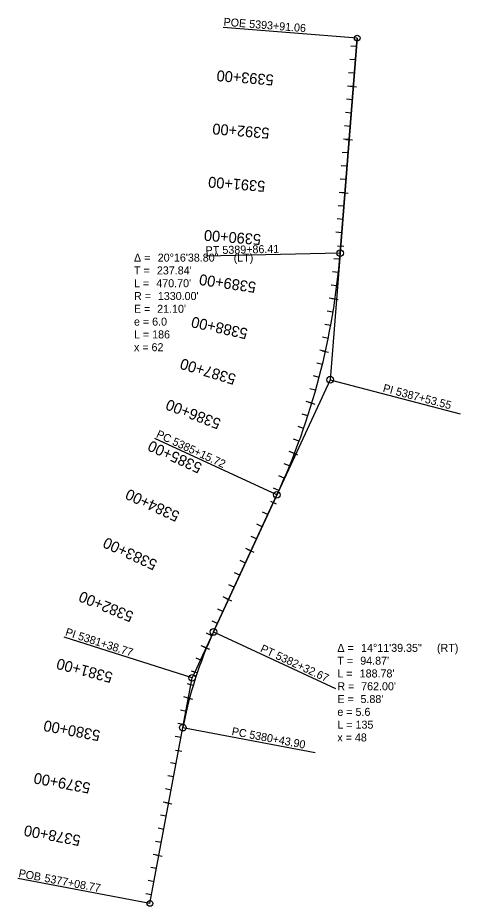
# Model space of a CAD drawing. Extents: x 20505953 to 20506782, y 7970566 to 7972232.
import ezdxf

# ---------------------------------------------------------------- set-up
doc = ezdxf.new("R2010")
doc.units = 0
for name, color, linetype in [('Alignment', 7, 'Continuous'), ('TextAlignment', 7, 'Continuous'), ('TextAlignmentLrg', 7, 'Continuous'), ('TextAlignmentSml', 7, 'Continuous')]:
    doc.layers.add(name, color=color, linetype=linetype)

msp = doc.modelspace()

# ---------------------------------------------------------------- linework, layer by layer
at = {"layer": 'Alignment'}
for p, q in [((20506589.2, 7972193.7), (20506538.4, 7971553.3)), ((20506589.2, 7972193.7), (20506557.2, 7971790.4)), ((20506557.2, 7971790.4), (20506589.2, 7972193.7)), ((20506538.4, 7971553.3), (20506280, 7970994.4)), ((20506319.9, 7971080.5), (20506438.6, 7971337.4)), ((20506200.8, 7970571.7), (20506280, 7970994.4)), ((20506200.8, 7970571.7), (20506262.6, 7970901.1)), ((20506200.8, 7970571.7), (20506262.6, 7970901.1))]:
    msp.add_line(p, q, dxfattribs=at)
for centre, radius, start, end in [((20505231.4, 7971895.5), 1330, 335.1875, 355.465), ((20505231.4, 7971895.5), 1330, 335.1875, 355.465), ((20507011.5, 7970760.7), 762, 155.1875, 169.3818), ((20507011.5, 7970760.7), 762, 155.1875, 169.3818)]:
    msp.add_arc(centre, radius, start, end, dxfattribs=at)
at = {"layer": 'TextAlignment'}
for p, q in [((20506589.2, 7972193.7), (20506338, 7972213.7)), ((20506338, 7972213.7), (20506338, 7972213.7)), ((20506306, 7971810.3), (20506306, 7971810.3)), ((20506557.2, 7971790.4), (20506305.3, 7971785)), ((20506538.4, 7971553.3), (20506782.2, 7971489.4)), ((20506782.2, 7971489.4), (20506782.2, 7971489.4)), ((20506438.6, 7971337.4), (20506209.9, 7971443.1)), ((20506209.9, 7971443.1), (20506209.9, 7971443.1)), ((20506280, 7970994.4), (20506040, 7971071)), ((20506040, 7971071), (20506040, 7971071)), ((20506319.9, 7971080.5), (20506548.6, 7970974.7)), ((20506548.6, 7970974.7), (20506548.6, 7970974.7)), ((20506262.6, 7970901.1), (20506510.2, 7970854.7)), ((20506510.2, 7970854.7), (20506510.2, 7970854.7)), ((20506200.8, 7970571.7), (20505953.1, 7970618.2)), ((20505953.1, 7970618.2), (20505953.1, 7970618.2))]:
    msp.add_line(p, q, dxfattribs=at)
for centre, radius in [((20506589.2, 7972193.7), 5.34), ((20506557.2, 7971790.4), 6.24), ((20506538.4, 7971553.3), 6.24), ((20506438.6, 7971337.4), 6.24), ((20506319.9, 7971080.5), 6.24), ((20506280, 7970994.4), 6.24), ((20506262.6, 7970901.1), 6.24), ((20506200.8, 7970571.7), 5.34)]:
    msp.add_circle(centre, radius, dxfattribs=at)
at = {"layer": 'TextAlignmentLrg'}
for p, q in [((20506582, 7972103), (20506571.2, 7972103.8)), ((20506574.1, 7972003.3), (20506563.2, 7972004.1)), ((20506566.2, 7971903.6), (20506555.3, 7971904.4)), ((20506552.2, 7971804.4), (20506564.4, 7971803.4)), ((20506547.6, 7971704.5), (20506536.8, 7971706.1)), ((20506529.6, 7971606.2), (20506518.9, 7971608.5)), ((20506504.1, 7971509.5), (20506493.7, 7971512.6)), ((20506471.6, 7971415), (20506461.4, 7971418.9)), ((20506426.5, 7971325.7), (20506437.6, 7971320.5)), ((20506390.1, 7971232.3), (20506380.2, 7971236.9)), ((20506348.1, 7971141.6), (20506338.2, 7971146.2)), ((20506306.8, 7971050.5), (20506296.7, 7971054.7)), ((20506274.9, 7970955.8), (20506264.4, 7970958.6)), ((20506248.5, 7970859.1), (20506260.5, 7970856.8)), ((20506236, 7970759.7), (20506225.3, 7970761.7)), ((20506217.6, 7970661.4), (20506206.9, 7970663.4))]:
    msp.add_line(p, q, dxfattribs=at)
at = {"layer": 'TextAlignmentSml'}
for p, q in [((20506588, 7972177.7), (20506577.1, 7972178.6)), ((20506586, 7972152.8), (20506575.1, 7972153.7)), ((20506584, 7972127.9), (20506573.1, 7972128.7)), ((20506575.9, 7972103.4), (20506588.1, 7972102.5)), ((20506580.1, 7972078), (20506569.2, 7972078.9)), ((20506578.1, 7972053.1), (20506567.2, 7972054)), ((20506576.1, 7972028.2), (20506565.2, 7972029.1)), ((20506568, 7972003.8), (20506580.2, 7972002.8)), ((20506572.2, 7971978.4), (20506561.3, 7971979.2)), ((20506570.2, 7971953.4), (20506559.3, 7971954.3)), ((20506568.2, 7971928.5), (20506557.3, 7971929.4)), ((20506560.1, 7971904.1), (20506572.3, 7971903.1)), ((20506564.2, 7971878.7), (20506553.4, 7971879.5)), ((20506562.3, 7971853.7), (20506551.4, 7971854.6)), ((20506560.3, 7971828.8), (20506549.4, 7971829.7)), ((20506552.2, 7971804.4), (20506564.4, 7971803.4)), ((20506556.3, 7971779), (20506545.4, 7971779.9)), ((20506553.9, 7971754.1), (20506543, 7971755.3)), ((20506551, 7971729.3), (20506540.1, 7971730.6)), ((20506541.6, 7971705.4), (20506553.7, 7971703.6)), ((20506543.8, 7971679.8), (20506533, 7971681.6)), ((20506539.5, 7971655.2), (20506528.8, 7971657.1)), ((20506534.8, 7971630.6), (20506524.1, 7971632.8)), ((20506523.6, 7971607.5), (20506535.5, 7971604.8)), ((20506523.9, 7971581.8), (20506513.3, 7971584.4)), ((20506517.8, 7971557.6), (20506507.2, 7971560.4)), ((20506511.2, 7971533.5), (20506500.7, 7971536.4)), ((20506498.3, 7971511.2), (20506510, 7971507.7)), ((20506496.7, 7971485.6), (20506486.3, 7971489)), ((20506488.7, 7971461.9), (20506478.4, 7971465.5)), ((20506480.4, 7971438.4), (20506470.1, 7971442.1)), ((20506465.8, 7971417.2), (20506477.3, 7971412.7)), ((20506462.3, 7971391.7), (20506452.2, 7971395.9)), ((20506452.6, 7971368.7), (20506442.6, 7971373)), ((20506442.5, 7971345.8), (20506432.6, 7971350.3)), ((20506426.5, 7971325.7), (20506437.6, 7971320.5)), ((20506421.5, 7971300.4), (20506411.6, 7971305)), ((20506411.1, 7971277.7), (20506401.1, 7971282.3)), ((20506400.6, 7971255), (20506390.6, 7971259.6)), ((20506384.5, 7971234.9), (20506395.6, 7971229.8)), ((20506379.6, 7971209.7), (20506369.7, 7971214.2)), ((20506369.1, 7971187), (20506359.2, 7971191.5)), ((20506358.6, 7971164.3), (20506348.7, 7971168.9)), ((20506342.5, 7971144.1), (20506353.7, 7971139)), ((20506337.6, 7971118.9), (20506327.7, 7971123.5)), ((20506327.1, 7971096.2), (20506317.2, 7971100.8)), ((20506316.7, 7971073.5), (20506306.7, 7971078)), ((20506301.1, 7971052.9), (20506312.4, 7971048.2)), ((20506297.7, 7971027.3), (20506287.4, 7971031.1)), ((20506289.3, 7971003.7), (20506278.9, 7971007.2)), ((20506281.7, 7970979.9), (20506271.3, 7970983)), ((20506269, 7970957.4), (20506280.8, 7970954.2)), ((20506268.9, 7970931.5), (20506258.3, 7970934)), ((20506263.7, 7970907.1), (20506253, 7970909.2)), ((20506259.1, 7970882.5), (20506248.3, 7970884.5)), ((20506248.5, 7970859.1), (20506260.5, 7970856.8)), ((20506249.9, 7970833.4), (20506239.1, 7970835.4)), ((20506245.3, 7970808.8), (20506234.5, 7970810.8)), ((20506240.6, 7970784.2), (20506229.9, 7970786.3)), ((20506230, 7970760.8), (20506242.1, 7970758.5)), ((20506231.4, 7970735.1), (20506220.7, 7970737.1)), ((20506226.8, 7970710.5), (20506216.1, 7970712.5)), ((20506222.2, 7970686), (20506211.5, 7970688)), ((20506211.6, 7970662.5), (20506223.6, 7970660.3)), ((20506213, 7970636.8), (20506202.3, 7970638.8)), ((20506208.4, 7970612.2), (20506197.7, 7970614.3)), ((20506203.8, 7970587.7), (20506193.1, 7970589.7))]:
    msp.add_line(p, q, dxfattribs=at)

# ---------------------------------------------------------------- texts
at = {"layer": 'TextAlignment'}
for s, rotation, p in [('POE ', 355.465, (20506338.3, 7972216.9)), ('5393+91.06', 355.465, (20506386.3, 7972213.1)), ('PT', 1.2175, (20506305.2, 7971788.3)), ('5389+86.41', 1.2175, (20506336.7, 7971789)), ('PI ', 345.3262, (20506636.2, 7971531.1)), ('5387+53.55', 345.3262, (20506660.4, 7971524.7)), ('PC', 335.1875, (20506211.3, 7971446.1)), ('5385+15.72', 335.1875, (20506241.5, 7971432.1)), ('PI ', 342.2847, (20506041, 7971074.2)), ('5381+38.77', 342.2847, (20506064.8, 7971066.6)), ('PT', 335.1875, (20506406.3, 7971044.1)), ('5382+32.67', 335.1875, (20506434.9, 7971030.9)), ('PC', 349.3818, (20506353.1, 7970887.5)), ('5380+43.90', 349.3818, (20506385.9, 7970881.3)), ('POB ', 349.3818, (20505953.7, 7970621.4)), ('5377+08.77', 349.3818, (20506002.2, 7970612.3))]:
    msp.add_text(s, height=15, rotation=rotation, dxfattribs=at).set_placement(p)
for s, p in [('Δ = ', (20506170.9, 7971774.7)), ('20°16\'38.80"', (20506215.4, 7971774.7)), (' (LT)', (20506352.1, 7971774.7)), ('T = ', (20506170.9, 7971750.7)), ("237.84'", (20506213.8, 7971750.7)), ('L = ', (20506170.9, 7971726.7)), ("470.70'", (20506212.7, 7971726.7)), ('R = ', (20506170.9, 7971702.7)), ("1330.00'", (20506215.6, 7971702.7)), ('E = ', (20506170.9, 7971678.7)), ("21.10'", (20506214.3, 7971678.7)), ('e = 6.0', (20506170.9, 7971654.7)), ('L = 186', (20506170.9, 7971630.7)), ('x = 62', (20506170.9, 7971606.7)), ('Δ = ', (20506552, 7971043.2)), ('14°11\'39.35"', (20506596.4, 7971043.2)), (' (RT)', (20506733.1, 7971043.2)), ('T = ', (20506552, 7971019.2)), ("94.87'", (20506594.9, 7971019.2)), ('L = ', (20506552, 7970995.2)), ("188.78'", (20506593.8, 7970995.2)), ("762.00'", (20506596.6, 7970971.2)), ('R = ', (20506552, 7970971.2)), ('E = ', (20506552, 7970947.2)), ("5.88'", (20506595.3, 7970947.2)), ('e = 5.6', (20506552, 7970923.2)), ('L = 135', (20506552, 7970899.2)), ('x = 48', (20506552, 7970875.2))]:
    msp.add_text(s, height=15, dxfattribs=at).set_placement(p)
at = {"layer": 'TextAlignmentLrg'}
for s, rotation, p in [('5390+00', 175.465, (20506409.6, 7971825.9)), ('5385+00', 155.1875, (20506300.2, 7971395.3)), ('5380+00', 169.3818, (20506108.9, 7970895.6))]:
    msp.add_text(s, height=20.4, rotation=rotation, dxfattribs=at).set_placement(p)
at = {"layer": 'TextAlignmentSml'}
for s, rotation, p in [('5393+00', 175.465, (20506433.3, 7972125)), ('5392+00', 175.465, (20506425.4, 7972025.3)), ('5391+00', 175.465, (20506417.5, 7971925.6)), ('5390+00', 175.465, (20506409.6, 7971825.9)), ('5389+00', 171.7423, (20506400.6, 7971736.1)), ('5388+00', 167.4344, (20506385.4, 7971648.8)), ('5387+00', 163.1264, (20506363.6, 7971562.8)), ('5386+00', 158.8184, (20506335.4, 7971478.7)), ('5385+00', 155.1875, (20506300.2, 7971395.3)), ('5384+00', 155.1875, (20506258.2, 7971304.6)), ('5383+00', 155.1875, (20506216.2, 7971213.8)), ('5382+00', 157.6442, (20506171.9, 7971117)), ('5381+00', 165.1634, (20506132.5, 7971004.1)), ('5380+00', 169.3818, (20506108.9, 7970895.6)), ('5379+00', 169.3818, (20506090.5, 7970797.3)), ('5378+00', 169.3818, (20506072.1, 7970699))]:
    msp.add_text(s, height=20.4, rotation=rotation, dxfattribs=at).set_placement(p)

doc.saveas('drawing.dxf')
